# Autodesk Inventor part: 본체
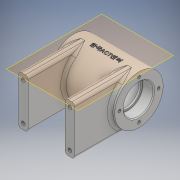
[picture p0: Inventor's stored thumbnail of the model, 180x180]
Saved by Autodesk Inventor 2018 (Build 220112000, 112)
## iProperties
Created: 2020-07
Part Number: 본체
Material: Generic
Document SubType Name: Modeling
Designer: Administrator
Density: 1 g/cm^3
Appearance: Default
Author: Administrator
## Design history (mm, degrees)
sketch "스케치1"
  geometry: L1 (-35, 0)-(35, 0); L2 (-35, 26)-(-35, 0); L3 (-35, 26)-(35, 26); L4 (35, 26)-(35, 0); L5 (-35, 16)-(-23, 16); L6 (-23, 16)-(-23, 14); L7 (-23, 14)-(-21, 14); L8 (-21, 14)-(-21, 21); L9 (-21, 21)-(21, 21); L10 (21, 21)-(21, 14); L11 (21, 14)-(23, 14); L12 (23, 14)-(23, 16); L13 (23, 16)-(35, 16); 3 further points
  constraints: 26 end point, 7 perpendicular, 6 point on line, 2 horizontal, 2 midpoint, 1 coincident, 1 vertical, 1 vertical alignment
  dimensions: "d0" = 70 distance of L1.start L1.end; "d1" = 32 diameter of L5 L1; "d2" = 42 diameter of L9 L1; "d3" = 52 diameter of L3 L1; "d4" = 12 distance of L5.start L5.end; "d5" = 12 distance of L12.end L13.end; "d7" = 28 diameter of L7 L1; "d8" = 42 distance of L8.end L9.end
revolve "회전1" sketch "스케치1" stored, may be unused: angle "d9" = 90 deg
node "작업 평면1"
sketch "스케치2"
  geometry: L1 (30, -26)-(30, 26); L2 (30, 26)-(20, 26); L3 (20, 26)-(20, -26); L4 (20, -26)-(30, -26); L5 (-20, -26)-(-30, -26); L6 (-30, -26)-(-30, 26); L7 (-30, 26)-(-20, 26); L8 (-20, 26)-(-20, -26); 2 further points
  constraints: 16 end point, 4 perpendicular, 2 horizontal alignment, 2 parallel, 1 horizontal, 1 midpoint, 1 vertical
  dimensions: "d11" = 60 distance between parallel lines of L6 L1; "d12" = 10 distance of L1.end L2.end; "d13" = 10 distance of L6.end L7.end; "d16" = 20 distance from line of point (0, 0) L3; "d19" = 52 distance of L1.start L1.end; "d20" = 52 distance of L5.end L6.end
extrude "돌출1" join sketch "스케치2" stored distance "d17" = 10; taper "d18" = 0 deg
node "작업 평면2"
sketch "스케치3"
  geometry: C1 r 5 at (0, 0); 1 further point
  constraints: 1 centre point, 1 coincident
  dimensions: "d22" = 10 diameter of C1
extrude "돌출2" join sketch "스케치3" stored distance "d23" = 10; taper "d24" = 0 deg
sketch "스케치4"
  geometry: C1 r 21 at (0, 0); 3 further points
  constraints: 2 vertical alignment, 1 centre point, 1 coincident, 1 other
  dimensions: "d25" = 42 diameter of C1
hole "구멍1" sketch "스케치4" at (0, 21) diameter "d26" = 3.242; stored, may be unused: countersink angle "d30" = 90 deg, drill point angle "d32" = 118 deg; dims "d27" = 8, "d28" = 4, "d29" = 2, "d31" = 10
fillet "모깎기1" dims "d36" = 3
fillet "모깎기2" dims "d37" = 3
fillet "모깎기3" dims "d38" = 3
chamfer "모따기1" distance "d39" = 1; stored, may be unused: second distance "d40" = 2, angle "d41" = 45 deg
fillet "모깎기4" dims "d42" = 2
hole "구멍2" diameter "d50" = 5.188; stored, may be unused: countersink angle "d54" = 90 deg, drill point angle "d56" = 118 deg; dims "d48" = 10, "d49" = 10, "d51" = 12, "d52" = 4, "d53" = 2, "d55" = 16
sketch "스케치6"
  geometry: L1 (0, 0)-(-48.238, -17.557); L2 (0, 26)-(-64, 26) reference; L3 (-27.251, -9.919)-(-25.199, -15.557); L4 (-25.199, -15.557)-(-20.535, -13.859); L5 (-20.535, -13.859)-(-22.587, -8.221); C1 r 14 at (0, 0) reference; A1 r 29 centre (0, 0) between (-17.664, 23) and (-17.664, -23) reference; 1 further point
  constraints: 8 end point, 2 parallel, 2 point on line, 1 perpendicular
  dimensions: "d58" = 20 deg angle of L2 L1; "d59" = 29 distance from line of point (0, 0) L3; "d60" = 12 diameter of L4 L1; "d61" = 4.96314 distance between parallel lines of L5 L3; "d62" = 43.55733 distance from line of L1.end L2
revolve "회전2" sketch "스케치6" stored, may be unused: angle "d63" = 90 deg
hole "구멍3" diameter "d66" = 5.188; stored, may be unused: countersink angle "d70" = 90 deg, drill point angle "d72" = 118 deg; dims "d64" = 10, "d65" = 10, "d67" = 12, "d68" = 4, "d69" = 2, "d71" = 16
fillet "모깎기5" dims "d73" = 2
sketch "스케치7"
  geometry: 3 further points
  constraints: 1 vertical alignment
  dimensions: "d74" = 25 horizontal distance of point (0, 0) point (25, -20); "d75" = 40 distance of point (25, 20) point (25, -20); "d76" = 20 vertical distance of point (0, 0) point (25, -20)
hole "구멍4" sketch "스케치7" at (25, -20), (25, 20) diameter "d77" = 4.134; stored, may be unused: countersink angle "d81" = 90 deg, drill point angle "d83" = 118 deg; dims "d78" = 8, "d79" = 4, "d80" = 2, "d82" = 10
fillet "모깎기6" dims "d84" = 3
fillet "모깎기7" dims "d85" = 0.3
node "작업 평면4"
sketch "스케치8"
  geometry: L1 (-35, 26)-(35, 26) reference; L2 (-35, -26)-(-35, 26) reference; 2 further points
  constraints: 1 other
  dimensions: "d86" = 26 distance from line of L1 point (0, 0); "d87" = 35 distance from line of point (0, 0) L2
feature "엠보싱1" sketch "스케치8" dims "d0" = 70, "d1" = 32, "d2" = 42, "d3" = 52, "d4" = 12, "d5" = 12, "d7" = 28, "d8" = 42, "d88" = 0.5, "d89" = 0
node "솔리드1"
pattern_circular "원형 패턴1" dims angle "d34" = 360 deg
mirror "미러1"
mirror "미러2"
other parameters: "d10" = -64, "d21" = 29
